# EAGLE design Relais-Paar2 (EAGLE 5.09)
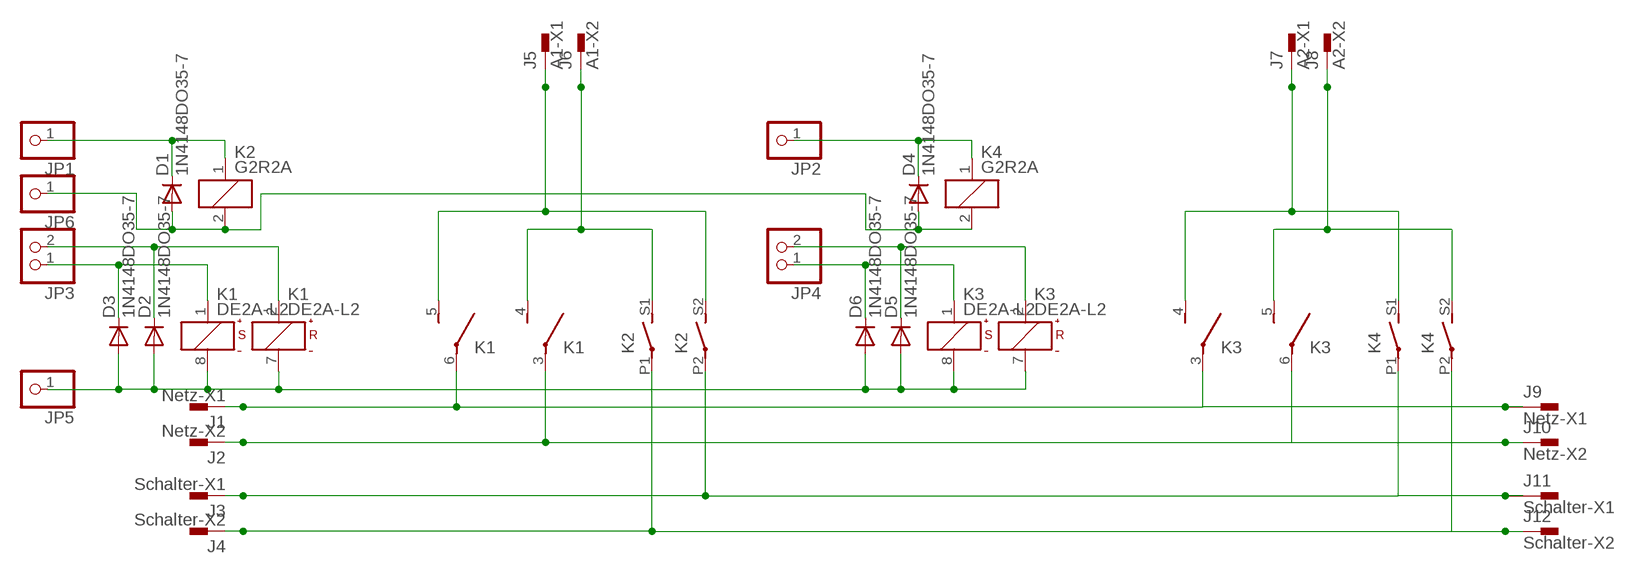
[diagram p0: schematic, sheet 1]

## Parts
D1  1N4148DO35-7  DIODE-MINIMELF  [MINIMELF]
D2  1N4148DO35-7  DIODE-MINIMELF  [MINIMELF]
D3  1N4148DO35-7  DIODE-MINIMELF  [MINIMELF]
D4  1N4148DO35-7  DIODE-MINIMELF  [MINIMELF]
D5  1N4148DO35-7  DIODE-MINIMELF  [MINIMELF]
D6  1N4148DO35-7  DIODE-MINIMELF  [MINIMELF]
J1  Netz-X1  PIN2F061.080  [F061.080]
J2  Netz-X2  PIN2F061.080  [F061.080]
J3  Schalter-X1  PIN2F061.080  [F061.080]
J4  Schalter-X2  PIN2F061.080  [F061.080]
J5  A1-X1  PIN2F061.080  [F061.080]
J6  A1-X2  PIN2F061.080  [F061.080]
J7  A2-X1  PIN2F061.080  [F061.080]
J8  A2-X2  PIN2F061.080  [F061.080]
J9  Netz-X1  PIN2F061.080  [F061.080]
J10  Netz-X2  PIN2F061.080  [F061.080]
J11  Schalter-X1  PIN2F061.080  [F061.080]
J12  Schalter-X2  PIN2F061.080  [F061.080]
JP1  PINHD-1X1  [1X01]
JP2  PINHD-1X1  [1X01]
JP3  PINHD-1X2  [1X02]
JP4  PINHD-1X2  [1X02]
JP5  PINHD-1X1  [1X01]
JP6  PINHD-1X1  [1X01]
K1  DE2A-L2  [DE2A-L2]
K2  G2R2A  [G2R2A]
K3  DE2A-L2  [DE2A-L2]
K4  G2R2A  [G2R2A]

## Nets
N$1 [mains]: J1.1A J1.1B(1.1) J9.1A J9.1B(1.1) K1.6(S2:P) K3.3(S1:P)
N$2 [mains]: J2.1A J2.1B(1.1) J10.1A J10.1B(1.1) K1.3(S1:P) K3.6(S2:P)
N$3 [mains]: J5.1A J5.1B(1.1) K1.5(S2:S) K2.S2(3:S)
N$4 [mains]: J6.1A J6.1B(1.1) K1.4(S1:S) K2.S1(2:S)
N$5 [mains]: J4.1A J4.1B(1.1) J12.1A J12.1B(1.1) K2.P1(2:P) K4.P2(3:P)
N$6 [mains]: J3.1A J3.1B(1.1) J11.1A J11.1B(1.1) K2.P2(3:P) K4.P1(2:P)
N$7: D2.A D3.A D5.A D6.A JP5.1 K1.7(R:-) K1.8(S:-) K3.7(R:-) K3.8(S:-)
N$8: D3.C JP3.1 K1.1(S:+)
N$9: D2.C JP3.2 K1.2(R:+)
N$11: D1.C JP1.1 K2.1
N$13: D1.A D4.A JP6.1 K2.2 K4.2
N$14 [mains]: J7.1A J7.1B(1.1) K3.4(S1:S) K4.S1(2:S)
N$15 [mains]: J8.1A J8.1B(1.1) K3.5(S2:S) K4.S2(3:S)
N$19: D6.C JP4.1 K3.1(S:+)
N$20: D5.C JP4.2 K3.2(R:+)
N$22: D4.C JP2.1 K4.1

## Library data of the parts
D1-D6 = diode:DIODE-: DIODE
J1-J12 = con-faston:PIN2: Flachstecker Typ Tyco/Electronics/AMP TAB, FASTON
JP1 JP2 JP5 JP6 = pinhead:PINHD-1X1: PIN HEADER
JP3 JP4 = pinhead:PINHD-1X2: PIN HEADER
K1 K3 = 11my-mechanics:DE2A-L2*: MINIATURE RELAY NAiS DE2a-L2 Source: Pollin
K2 K4 = relay:G2R2A: RELAY 2 x norm. open, Omron

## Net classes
1 mains: width 4 mm, clearance 2 mm

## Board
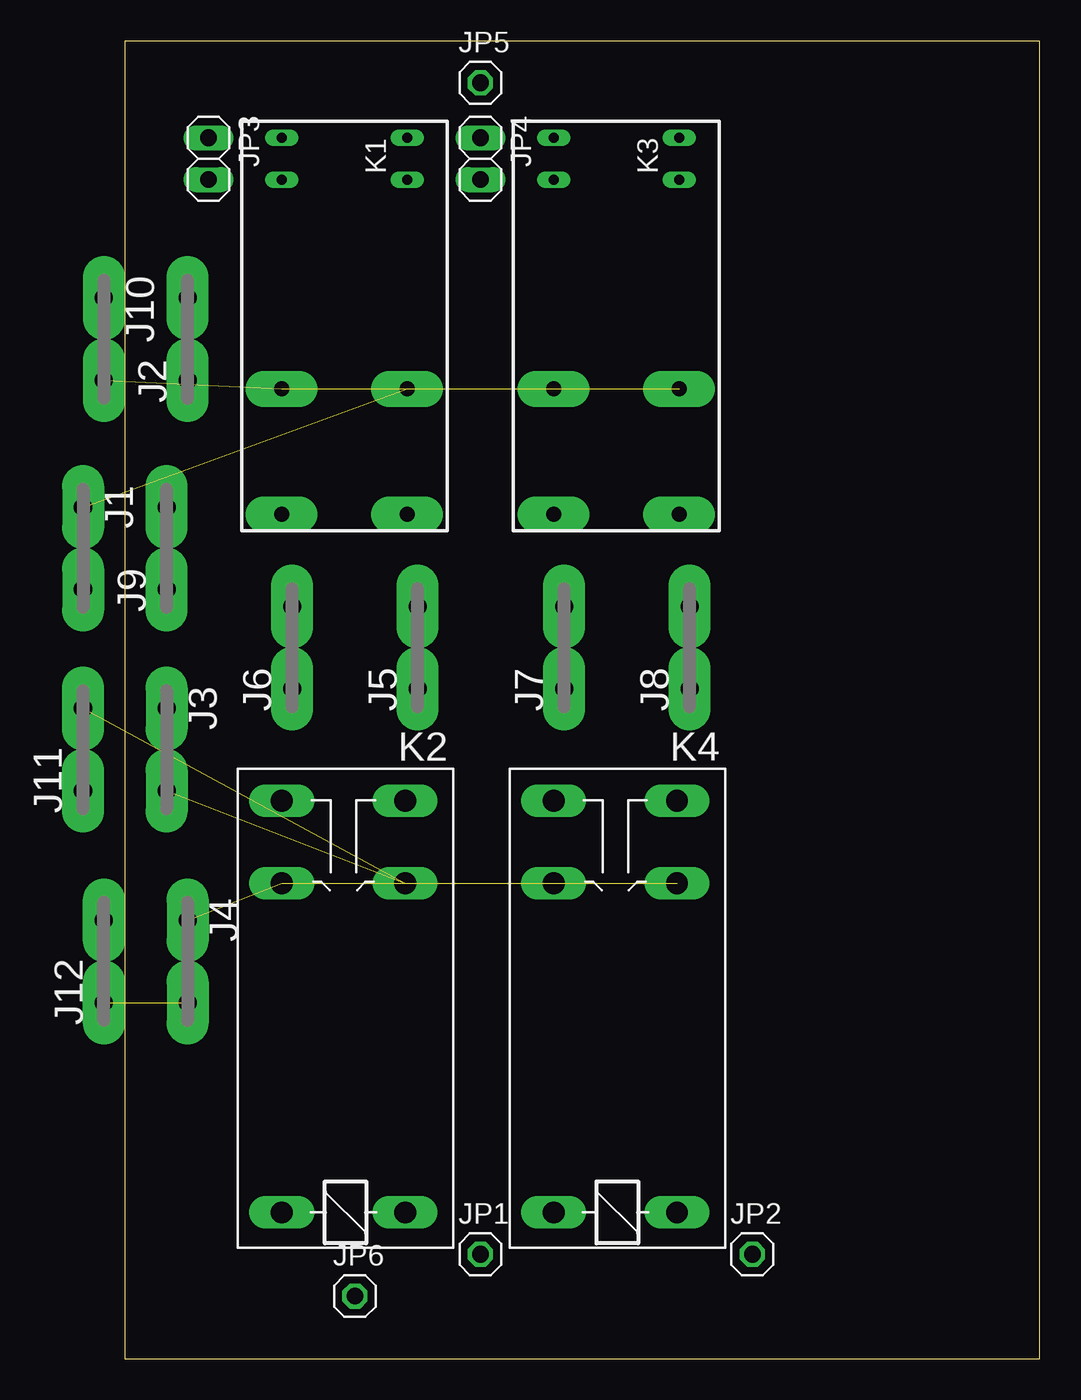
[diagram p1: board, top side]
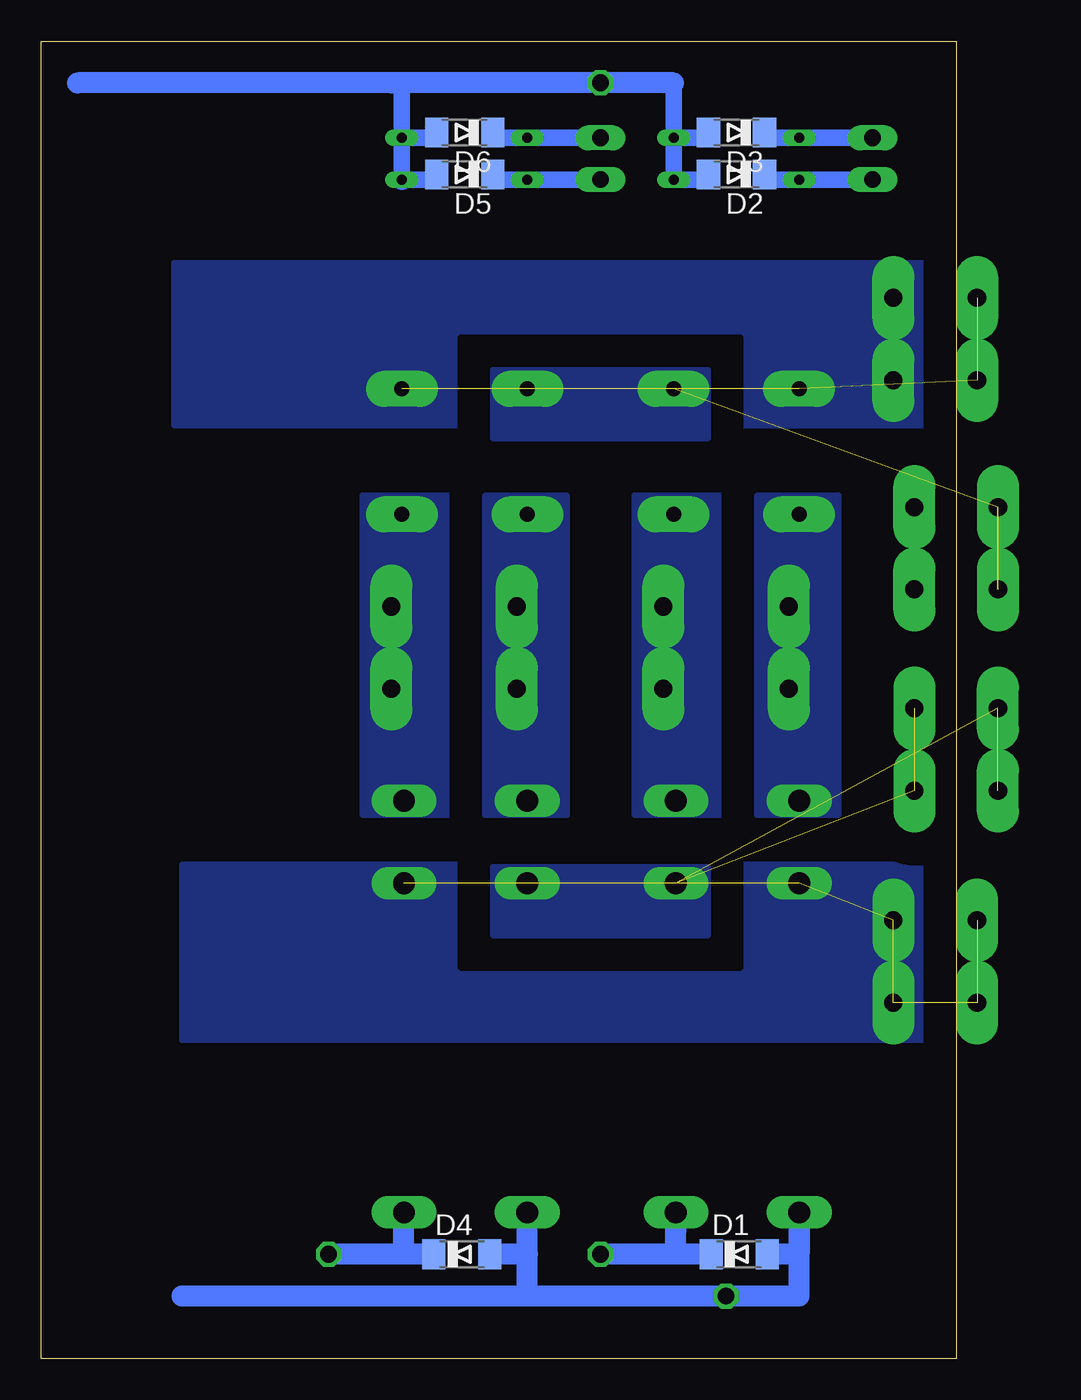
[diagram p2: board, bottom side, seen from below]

Size 55.55 x 80 mm. Coordinates in mm from the lower left corner, seen from the top.
Outline: 0,0 55.55,0 55.55,80 0,80 0,0
Copper layers (1+2*15+16): Top 0.035mm / dielectric 0.36mm / layer 2 0.018mm / dielectric 0.71mm / layer 15 0.018mm / dielectric 0.36mm / Bottom 0.035mm
Design rules "q-print.info": minimum track width 6mil, minimum drill 0.3mm, track to track 6mil, track to pad 6mil, pad to pad 6mil, via to via 6mil, smd to smd 6mil, copper to edge 8mil, drill to drill 10mil, minimum pad ring 8mil, minimum via ring 8mil, stop-mask expansion 4mil, vias tented up to drill 16mil, thermal gap 10mil

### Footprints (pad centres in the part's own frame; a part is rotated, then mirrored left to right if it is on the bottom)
MINIMELF = smd 1.4 x 1.8: A 1.7,0; C -1.7,0
F061.080 = drill 1.1 pad 2.54 long: 1A -2.5,0; 1B 2.5,0
1X01 = drill 1.016 octagon: 1 0,0
1X02 = drill 1.016 long: 1 -1.27,0; 2 1.27,0
DE2A-L2 = drill 0.61 long: 1 -8.89,-3.81; 2 -6.35,-3.81; 7 -6.35,3.81; 8 -8.89,3.81 | drill 0.9 pad 2.184 long: 3 6.35,-3.81; 4 13.97,-3.81; 5 13.97,3.81; 6 6.35,3.81
G2R2A = drill 1.321 long: 1 -2.54,-3.683; 2 -2.54,3.81; P1 17.45,3.81; P2 17.45,-3.683; S1 22.454,3.81; S2 22.454,-3.683

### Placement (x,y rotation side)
D1  13.18,6.35 0 bottom
D2  13.34,71.91 180 bottom
D3  13.33,74.45 180 bottom
D4  30,6.35 0 bottom
D5  29.84,71.91 180 bottom
D6  29.84,74.45 180 bottom
J1  -2.54,49.21 270 top
J2  3.81,61.91 90 top
J3  2.54,36.99 270 top
J4  3.81,24.13 270 top
J5  17.78,43.18 90 top
J6  10.16,43.18 90 top
J7  26.67,43.18 90 top
J8  34.29,43.18 90 top
J9  2.54,49.21 90 top
J10  -1.27,61.91 270 top
J11  -2.54,36.99 90 top
J12  -1.27,24.13 90 top
JP1  21.59,6.35 0 top
JP2  38.1,6.35 0 top
JP3  5.08,72.87 270 top
JP4  21.59,72.87 270 top
JP5  21.59,77.47 0 top
JP6  13.97,3.81 0 top
K1  13.34,65.25 270 top
K2  13.34,11.43 90 top
K3  29.84,65.25 270 top
K4  29.84,11.43 90 top

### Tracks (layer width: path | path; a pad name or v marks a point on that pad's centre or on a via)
N$1  (5 unrouted)
  pour Bottom (no thermals): 15.08,60.01 28.1,60.01 28.1,55.88 15.08,55.88
N$2  (5 unrouted)
  pour Bottom (isolate 2, rank 3, no thermals): 47.47,66.52 47.47,56.67 0.95,56.67 0.95,66.52
N$3
  pour Bottom (isolate 2, rank 4, no thermals): 13.34,33.02 19.53,33.02 19.53,52.39 13.34,52.39
N$4
  pour Bottom (isolate 2, no thermals): 7.14,52.39 7.14,33.02 12.06,33.02 12.07,52.39
N$5  (5 unrouted)
  pour Bottom (isolate 2, rank 2, no thermals): 1.27,19.37 1.27,30 46.99,30 46.99,19.37
N$6  (5 unrouted)
  pour Bottom (no thermals): 15.08,29.84 28.1,29.84 28.1,25.72 15.08,25.72
N$7
  Bottom 1.016: K1.8 15.04,74.14 D3.A | D2.A 15.04,71.6 K1.7 K1.8 | K3.8 31.55,74.14 D6.A | K1.8 17.14,77.47 | K3.8 K3.7 31.55,71.6 D5.A | K3.8 33.66,77.47 34.29,77.47
  Bottom 1.27: 17.14,77.47 JP5.1 34.29,77.47 53.34,77.47 | K3.7
N$8
  Bottom 1.016: D3.C 11.63,74.14 K1.1 JP3.1
N$9
  Bottom 1.016: D2.C 11.63,71.6 K1.2 JP3.2
N$11
  Bottom 1.27: JP1.1 17.05,6.35 17.02,8.92 K2.1 17.02,6.35 D1.C
N$13
  Bottom 1.27: 26.04,3.81 JP6.1 9.53,3.81 K2.2 9.53,6.35 D1.A | 26.04,3.81 26.04,6.35 | 26.04,6.35 K4.2 | 26.04,3.81 46.99,3.81 | 26.04,6.35 D4.A
N$14
  pour Bottom (isolate 2, no thermals): 28.57,52.39 23.65,52.39 23.65,33.02 28.57,33.02
N$15
  pour Bottom (isolate 2, rank 4, no thermals): 29.84,33.02 36.04,33.02 36.04,52.39 29.84,52.39
N$19
  Bottom 1.016: D6.C 28.14,74.14 K3.1 JP4.1
N$20
  Bottom 1.016: D5.C 28.14,71.6 K3.2 JP4.2
N$22
  Bottom 1.27: D4.C 33.53,6.35 | 33.53,6.35 K4.1 | 33.53,6.35 JP2.1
